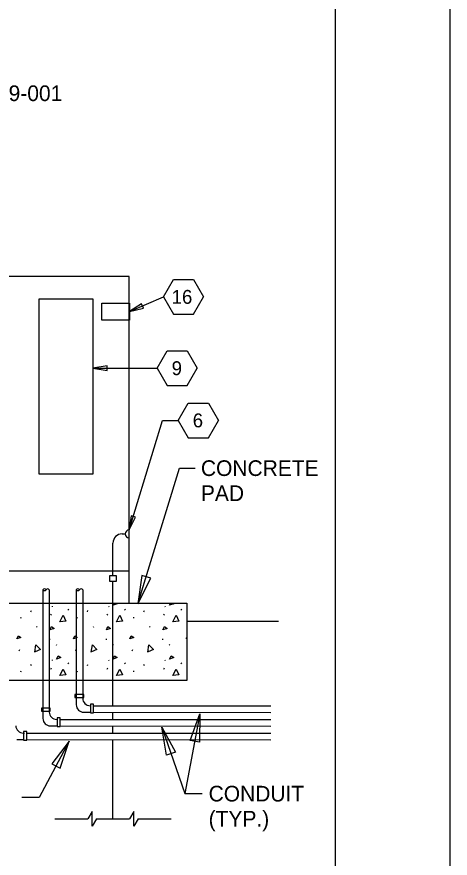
# Model space of a CAD drawing. Extents: x 359576 to 360896, y 1607020 to 1607868.
# Drawn here: x 360730.2 to 360895.9, y 1607381.3 to 1607703.4 of the extents above; entities that cross this region are included whole.
import ezdxf

# ---------------------------------------------------------------- set-up
doc = ezdxf.new("R2010")
doc.units = 0
for name, color, linetype in [('Default', 7, 'Continuous'), ('LaneLine_ep', 7, 'Continuous'), ('PlotBorder_dp', 7, 'Continuous'), ('SheetBorder_dp', 7, 'Continuous')]:
    doc.layers.add(name, color=color, linetype=linetype)

msp = doc.modelspace()

# ---------------------------------------------------------------- linework, layer by layer
at = {"layer": 'Default'}
for p, q in [((360786.28, 1607596.19), (360790.11, 1607602.83)), ((360790.11, 1607602.83), (360797.78, 1607602.83)), ((360797.78, 1607602.83), (360801.61, 1607596.19)), ((360786.28, 1607596.19), (360790.11, 1607589.55)), ((360797.78, 1607589.55), (360801.61, 1607596.19)), ((360790.11, 1607589.55), (360797.78, 1607589.55)), ((360783.85, 1607568.89), (360787.68, 1607575.53)), ((360787.68, 1607575.53), (360795.35, 1607575.53)), ((360795.35, 1607575.53), (360799.18, 1607568.89)), ((360783.85, 1607568.89), (360787.68, 1607562.25)), ((360795.35, 1607562.25), (360799.18, 1607568.89)), ((360787.68, 1607562.25), (360795.35, 1607562.25)), ((360791.91, 1607548.91), (360795.74, 1607555.54)), ((360795.74, 1607555.54), (360803.41, 1607555.54)), ((360803.41, 1607555.54), (360807.24, 1607548.91)), ((360791.91, 1607548.91), (360795.74, 1607542.27)), ((360803.41, 1607542.27), (360807.24, 1607548.91)), ((360795.74, 1607542.27), (360803.41, 1607542.27)), ((360770.43, 1607505.45), (360771.63, 1607505.45)), ((360766.93, 1607489.55), (360766.93, 1607501.95)), ((360668.76, 1607491.27), (360773.13, 1607491.27)), ((360766.93, 1607439.51), (360766.93, 1607487.27)), ((360740.11, 1607484.1), (360740.11, 1607434.8)), ((360742.57, 1607484.1), (360742.57, 1607437.27)), ((360752.9, 1607484.1), (360752.9, 1607440.04)), ((360755.37, 1607484.1), (360755.37, 1607442.5)), ((360635.06, 1607478.91), (360795.13, 1607478.91)), ((360743.62, 1607477.79), (360743.73, 1607477.56)), ((360749.72, 1607476.65), (360749.95, 1607476.31)), ((360765.22, 1607477.79), (360765.34, 1607477.56)), ((360771.32, 1607476.65), (360771.55, 1607476.31)), ((360786.83, 1607477.79), (360786.94, 1607477.56)), ((360792.93, 1607476.65), (360793.15, 1607476.31)), ((360795.13, 1607478.91), (360795.13, 1607449.39)), ((360731.65, 1607473.17), (360731.76, 1607473.63)), ((360735.53, 1607475.62), (360735.75, 1607476.08)), ((360743.16, 1607474.31), (360743.39, 1607474.77)), ((360753.25, 1607473.17), (360753.37, 1607473.63)), ((360757.13, 1607475.62), (360757.36, 1607476.08)), ((360764.77, 1607474.31), (360765, 1607474.77)), ((360774.86, 1607473.17), (360774.97, 1607473.63)), ((360778.73, 1607475.62), (360778.96, 1607476.08)), ((360786.37, 1607474.31), (360786.6, 1607474.77)), ((360830.27, 1607471.95), (360795.13, 1607471.95)), ((360737.69, 1607469.98), (360737.92, 1607469.75)), ((360759.3, 1607469.98), (360759.52, 1607469.75)), ((360780.9, 1607469.98), (360781.13, 1607469.75)), ((360742.71, 1607465.31), (360742.71, 1607464.85)), ((360764.31, 1607465.31), (360764.31, 1607464.85)), ((360785.91, 1607465.31), (360785.91, 1607464.85)), ((360731.08, 1607460.75), (360731.31, 1607461.2)), ((360745.27, 1607462.8), (360745.5, 1607463.14)), ((360752.68, 1607460.75), (360752.91, 1607461.2)), ((360766.88, 1607462.8), (360767.1, 1607463.14)), ((360774.29, 1607460.75), (360774.51, 1607461.2)), ((360788.48, 1607462.8), (360788.71, 1607463.14)), ((360735.53, 1607455.05), (360735.75, 1607455.5)), ((360743.16, 1607453.73), (360743.39, 1607454.19)), ((360743.62, 1607457.21), (360743.73, 1607456.98)), ((360749.72, 1607456.07), (360749.95, 1607455.73)), ((360757.13, 1607455.05), (360757.36, 1607455.5)), ((360764.77, 1607453.73), (360765, 1607454.19)), ((360765.22, 1607457.21), (360765.34, 1607456.98)), ((360771.32, 1607456.07), (360771.55, 1607455.73)), ((360778.73, 1607455.05), (360778.96, 1607455.5)), ((360786.37, 1607453.73), (360786.6, 1607454.19)), ((360786.83, 1607457.21), (360786.94, 1607456.98)), ((360792.93, 1607456.07), (360793.15, 1607455.73)), ((360731.65, 1607452.59), (360731.76, 1607453.05)), ((360753.25, 1607452.59), (360753.37, 1607453.05)), ((360774.86, 1607452.59), (360774.97, 1607453.05)), ((360795.13, 1607449.39), (360635.06, 1607449.39)), ((360737.69, 1607449.4), (360737.7, 1607449.39)), ((360759.3, 1607449.4), (360759.3, 1607449.39)), ((360780.9, 1607449.4), (360780.91, 1607449.39)), ((360758.22, 1607439.65), (360758.64, 1607439.65)), ((360827.34, 1607439.51), (360759.53, 1607439.51)), ((360755.75, 1607437.19), (360758.37, 1607437.19)), ((360827.34, 1607436.98), (360759.53, 1607437.04)), ((360766.93, 1607434.31), (360766.93, 1607437.04)), ((360742.96, 1607431.95), (360745.57, 1607431.95)), ((360745.42, 1607434.42), (360745.84, 1607434.42)), ((360827.34, 1607434.27), (360746.74, 1607434.27)), ((360827.34, 1607431.74), (360746.74, 1607431.81)), ((360766.93, 1607429.04), (360766.93, 1607431.77)), ((360732.62, 1607429.18), (360733.04, 1607429.18)), ((360827.34, 1607429.04), (360733.94, 1607429.04)), ((360730.16, 1607426.72), (360732.77, 1607426.72)), ((360827.34, 1607426.49), (360733.94, 1607426.57)), ((360766.93, 1607396.42), (360766.93, 1607426.54)), ((360744.63, 1607396.41), (360757.34, 1607396.42)), ((360758.96, 1607399.23), (360757.34, 1607396.42)), ((360758.96, 1607393.6), (360758.96, 1607399.23)), ((360760.58, 1607396.42), (360758.96, 1607393.6)), ((360760.58, 1607396.42), (360773.29, 1607396.42)), ((360774.91, 1607399.23), (360773.29, 1607396.42)), ((360774.91, 1607393.6), (360774.91, 1607399.23)), ((360776.53, 1607396.42), (360774.91, 1607393.6)), ((360776.53, 1607396.42), (360789.24, 1607396.42))]:
    msp.add_line(p, q, dxfattribs=at)
for points in [[(360773.13, 1607603.99), (360668.76, 1607603.99), (360668.76, 1607478.99), (360773.13, 1607478.99)], [(360738.73, 1607595.43), (360759.28, 1607595.43), (360759.28, 1607528.31), (360738.73, 1607528.31)], [(360773.26, 1607587.34), (360762.63, 1607587.34), (360762.63, 1607593.76), (360773.26, 1607593.76)], [(360765.7, 1607489.55), (360768.17, 1607489.55), (360768.17, 1607487.27), (360765.7, 1607487.27)], [(360755.74, 1607442.82), (360755.74, 1607443.99), (360752.39, 1607443.99), (360752.39, 1607442.82)], [(360742.94, 1607437.59), (360742.94, 1607438.75), (360739.59, 1607438.75), (360739.59, 1607437.59)], [(360759.53, 1607440.24), (360758.37, 1607440.24), (360758.37, 1607436.9), (360759.53, 1607436.9)], [(360746.74, 1607435.01), (360745.57, 1607435.01), (360745.57, 1607431.66), (360746.74, 1607431.66)], [(360733.94, 1607429.78), (360732.77, 1607429.78), (360732.77, 1607426.43), (360733.94, 1607426.43)]]:
    msp.add_lwpolyline(points, close=True, dxfattribs=at)
for points in [[(360768.28, 1607478.91), (360768.59, 1607478.7), (360766.99, 1607478.13)], [(360766.99, 1607478.13), (360767.34, 1607478.91)], [(360789.88, 1607478.91), (360790.19, 1607478.7), (360788.59, 1607478.13)], [(360788.59, 1607478.13), (360788.95, 1607478.91)], [(360746.64, 1607471.8), (360747.9, 1607474.31), (360748.92, 1607472.03), (360746.64, 1607471.8)], [(360768.24, 1607471.8), (360769.5, 1607474.31), (360770.52, 1607472.03), (360768.24, 1607471.8)], [(360789.85, 1607471.8), (360791.1, 1607474.31), (360792.13, 1607472.03), (360789.85, 1607471.8)], [(360742.82, 1607468.73), (360743.39, 1607469.98), (360744.42, 1607469.3), (360742.82, 1607468.73)], [(360764.43, 1607468.73), (360765, 1607469.98), (360766.02, 1607469.3), (360764.43, 1607468.73)], [(360786.03, 1607468.73), (360786.6, 1607469.98), (360787.62, 1607469.3), (360786.03, 1607468.73)], [(360730.17, 1607465.31), (360730.74, 1607466.45), (360731.65, 1607465.76), (360730.17, 1607465.31)], [(360751.77, 1607465.31), (360752.34, 1607466.45), (360753.25, 1607465.76), (360751.77, 1607465.31)], [(360773.37, 1607465.31), (360773.94, 1607466.45), (360774.86, 1607465.76), (360773.37, 1607465.31)], [(360794.98, 1607465.31), (360795.13, 1607465.61)], [(360795.13, 1607465.35), (360794.98, 1607465.31)], [(360737.01, 1607460.18), (360737.46, 1607463.03), (360739.17, 1607461.2), (360737.12, 1607460.29)], [(360758.61, 1607460.18), (360759.07, 1607463.03), (360760.78, 1607461.2), (360758.73, 1607460.29)], [(360780.21, 1607460.18), (360780.67, 1607463.03), (360782.38, 1607461.2), (360780.33, 1607460.29)], [(360745.39, 1607457.55), (360745.96, 1607458.81), (360746.98, 1607458.12), (360745.39, 1607457.55)], [(360766.99, 1607457.55), (360767.56, 1607458.81), (360768.59, 1607458.12), (360766.99, 1607457.55)], [(360788.59, 1607457.55), (360789.16, 1607458.81), (360790.19, 1607458.12), (360788.59, 1607457.55)], [(360746.64, 1607451.23), (360747.9, 1607453.73), (360748.92, 1607451.45), (360746.64, 1607451.23)], [(360768.24, 1607451.23), (360769.5, 1607453.73), (360770.52, 1607451.45), (360768.24, 1607451.23)], [(360789.85, 1607451.23), (360791.1, 1607453.73), (360792.13, 1607451.45), (360789.85, 1607451.23)], [(360743.39, 1607449.39), (360743.39, 1607449.4), (360743.41, 1607449.39)], [(360764.99, 1607449.39), (360765, 1607449.4), (360765.01, 1607449.39)], [(360786.59, 1607449.39), (360786.6, 1607449.4), (360786.61, 1607449.39)]]:
    msp.add_lwpolyline(points, dxfattribs=at)
for centre, radius, start, end in [((360773.13, 1607505.45), 1.5, 90, 270), ((360770.43, 1607501.95), 3.5, 90, 180), ((360740.72, 1607483.75), 0.708, 29.4643, 150.5357), ((360740.72, 1607484.45), 0.708, 209.4643, 330.5357), ((360741.96, 1607483.75), 0.708, 29.4643, 150.5357), ((360753.52, 1607483.75), 0.708, 29.4643, 150.5357), ((360753.52, 1607484.45), 0.708, 209.4643, 330.5357), ((360754.75, 1607483.75), 0.708, 29.4643, 150.5357), ((360758.22, 1607442.5), 2.85, 180, 270), ((360755.75, 1607440.04), 2.85, 180, 270), ((360742.96, 1607434.8), 2.85, 180, 270), ((360745.42, 1607437.27), 2.85, 180, 270), ((360732.62, 1607432.03), 2.85, 180, 270)]:
    msp.add_arc(centre, radius, start, end, dxfattribs=at)
at = {"layer": 'LaneLine_ep'}
for p, q in [((360773.26, 1607590.55), (360786.28, 1607596.19)), ((360800.2, 1607436.61), (360794.43, 1607406.02)), ((360785.57, 1607431.51), (360794.43, 1607406.02)), ((360750.14, 1607426.14), (360738.71, 1607404.55)), ((360794.43, 1607406.02), (360801.02, 1607406.02)), ((360738.71, 1607404.55), (360732.13, 1607404.55))]:
    msp.add_line(p, q, dxfattribs=at)
for points in [[(360777.86, 1607593.53), (360773.26, 1607590.55), (360778.57, 1607591.88)], [(360764.68, 1607569.79), (360759.28, 1607568.89), (360764.68, 1607567.99)], [(360773.85, 1607512.38), (360773.13, 1607506.95), (360775.57, 1607511.86)], [(360777.92, 1607489.55), (360776.49, 1607478.71), (360781.35, 1607488.5)], [(360796.43, 1607426.35), (360800.2, 1607436.61), (360799.97, 1607425.68)], [(360787.41, 1607420.73), (360785.57, 1607431.51), (360790.81, 1607421.92)], [(360746.69, 1607415.77), (360750.14, 1607426.14), (360743.51, 1607417.45)]]:
    msp.add_lwpolyline(points, close=True, dxfattribs=at)
for points in [[(360759.28, 1607568.89), (360783.85, 1607568.89)], [(360773.13, 1607506.95), (360785.92, 1607548.91), (360791.91, 1607548.91)], [(360776.49, 1607478.71), (360792.32, 1607530.63), (360798.31, 1607530.63)]]:
    msp.add_lwpolyline(points, dxfattribs=at)
at = {"layer": 'PlotBorder_dp'}
msp.add_lwpolyline([(359575.91, 1607019.59), (360895.91, 1607019.59), (360895.91, 1607867.59), (359575.91, 1607867.59)], close=True, dxfattribs=at)
at = {"layer": 'SheetBorder_dp'}
msp.add_line((360851.91, 1607859.59), (360851.91, 1607027.59), dxfattribs=at)

# ---------------------------------------------------------------- texts
at = {"layer": 'Default'}
msp.add_text('REFER TO FDOT PLANS, INDEX 639-001', height=6, dxfattribs=at).set_placement((360593.72, 1607671.15))
for s, height, p in [('16', 5.311, (360789.39, 1607593.54)), ('9', 5.31, (360789.38, 1607566.24)), ('6', 5.31, (360797.44, 1607546.26)), ('CONCRETE', 6, (360800.57, 1607527.63)), ('PAD', 6, (360800.57, 1607518.03)), ('CONDUIT', 6, (360803.52, 1607403.02)), ('(TYP.)', 6, (360803.52, 1607393.42))]:
    msp.add_text(s, height=height, rotation=360, dxfattribs=at).set_placement(p)

doc.saveas('drawing.dxf')
